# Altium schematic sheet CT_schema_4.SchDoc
size 283 x 147 mm
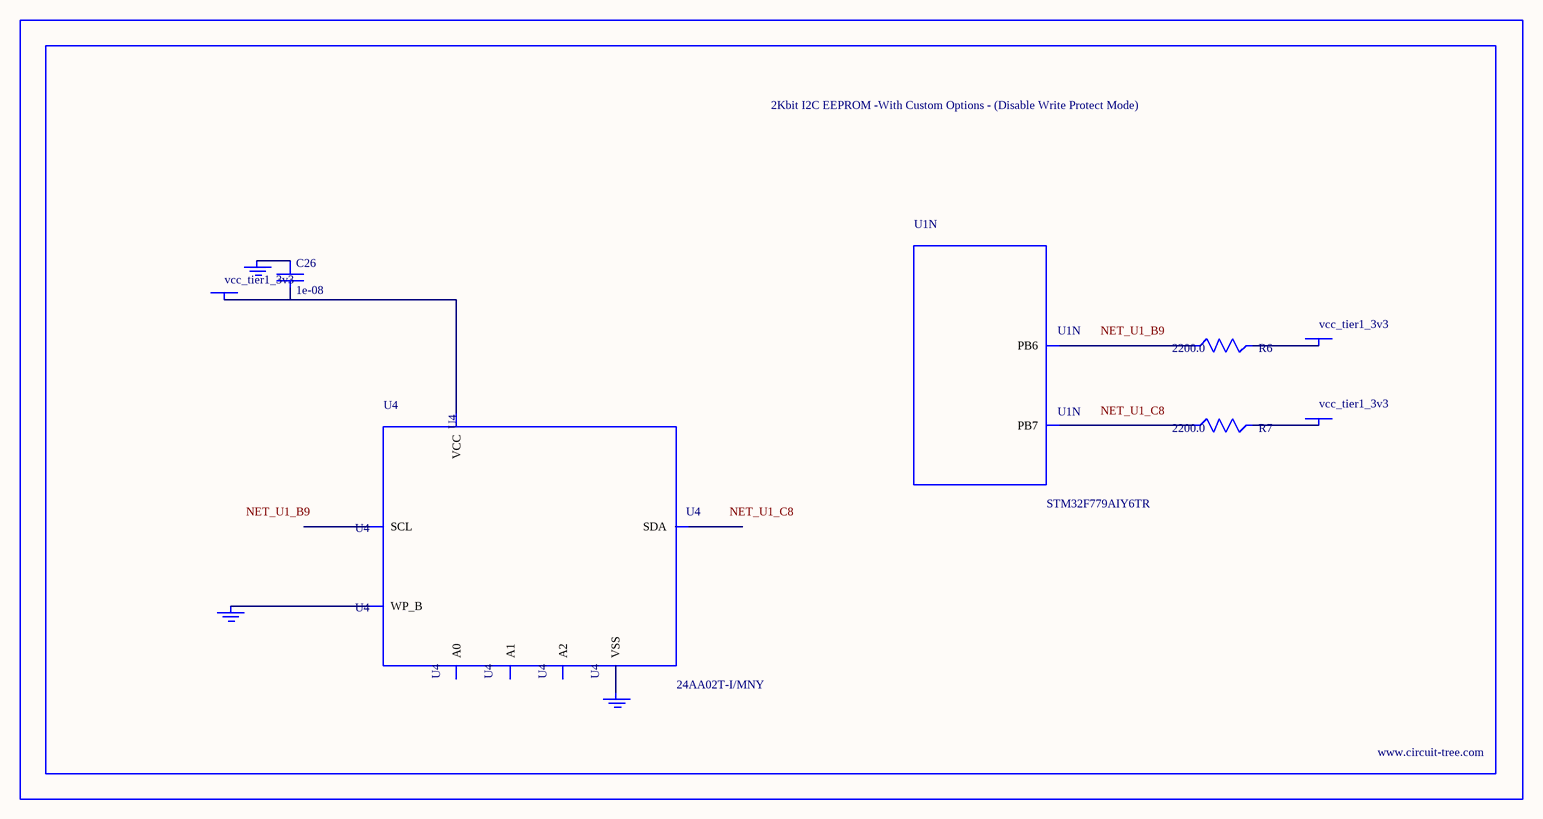
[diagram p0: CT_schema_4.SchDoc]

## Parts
BORDER3  (no value)
C26  1e-08  [C0402]
GND_INSTANCE_3_0  (no value)
GND_INSTANCE_3_1  (no value)
GND_INSTANCE_3_2  (no value)
POWER_INSTANCE_3_0  vcc_tier1_3v3
POWER_INSTANCE_3_1  vcc_tier1_3v3
POWER_INSTANCE_3_2  vcc_tier1_3v3
R6  2200.0  [R0603]
R7  2200.0  [R0603]
U1  STM32F779AIY6TR  [WLCSP180]  (part N of 15)
U4  24AA02T-I/MNY  [TDFN-8/6MM]

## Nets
NetC26_1: C26.1 GND_INSTANCE_3_1.0(GND)
NetC26_2: C26.2 POWER_INSTANCE_3_0.0(PWR) U4.8(VCC)
NetGND_INSTANCE_3_0_0: GND_INSTANCE_3_0.0(GND) U4.7(WP_B)
NetGND_INSTANCE_3_2_0: GND_INSTANCE_3_2.0(GND) U4.4(VSS)
NetPOWER_INSTANCE_3_1_0: POWER_INSTANCE_3_1.0(PWR) R6.2
NetPOWER_INSTANCE_3_2_0: POWER_INSTANCE_3_2.0(PWR) R7.2
NetR6_1: R6.1 U1.B9(PB6)
NetR7_1: R7.1 U1.C8(PB7)

Not connected (* = marked no-connect by the designer): U4 1(A0) 2(A1) 3(A2) 5(SDA) 6(SCL)

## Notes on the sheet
- Labels drawn without touching a wire or pin: NET_U1_B9, NET_U1_C8

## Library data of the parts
BORDER3 = BORDER_PAGE3
C26 = C0402C103K3RAC
GND_INSTANCE_3_0-GND_INSTANCE_3_2 = GND
POWER_INSTANCE_3_0-POWER_INSTANCE_3_2 = PWR
R6 R7 = RC0603JR-072K2L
